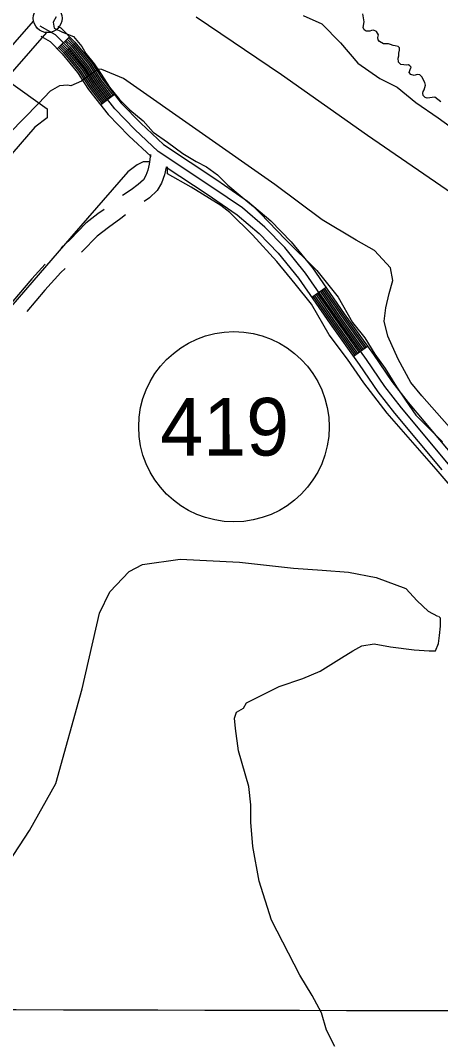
# Model space of a CAD drawing. Extents: x 3192927 to 3230760, y 831141 to 856475.
# Drawn here: x 3198677 to 3199405, y 842548 to 844320 of the extents above; entities that cross this region are included whole.
import ezdxf

# ---------------------------------------------------------------- set-up
doc = ezdxf.new("R2010")
doc.units = 0
for name, color, linetype in [('V-GRID-MAJR', 7, 'Continuous'), ('V-LEVE-TOET', 7, 'Continuous'), ('V-ROAD-CNTR', 7, 'Continuous'), ('V-ROAD-IDEN', 7, 'Continuous'), ('V-SITE-VEGE', 7, 'Continuous'), ('V-SURV-LINE', 7, 'Continuous'), ('V-TOPO-SHOR', 7, 'Continuous')]:
    doc.layers.add(name, color=color, linetype=linetype)

msp = doc.modelspace()

# ---------------------------------------------------------------- linework, layer by layer
at = {"layer": 'V-GRID-MAJR'}
msp.add_spline([(3197116.114, 842608.466), (3202348.431, 842596.67), (3207580.75, 842585.635), (3212813.071, 842575.361), (3218045.394, 842565.848), (3223277.717, 842557.096), (3228510.042, 842549.106), (3228510.043, 842549.106)], degree=3, dxfattribs=at)
at = {"layer": 'V-LEVE-TOET'}
for points in [[(3198981.377, 844326.688), (3199129.132, 844226.932), (3199278.042, 844121.2980000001), (3199443.6580000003, 844007.464)], [(3199511.485, 843511.42), (3199371.9590000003, 843669.481), (3199353.343, 843692.6780000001), (3199331.241, 843733.186), (3199313.022, 843772.9500000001), (3199307.142, 843798.767), (3199309.647, 843821.782), (3199315.779, 843846.985), (3199322.17, 843869.581), (3199317.8140000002, 843891.136), (3199290.275, 843921.698), (3199258.199, 843939.37), (3199199.245, 843974.59), (3199117.514, 844035.706), (3198855.103, 844219.471), (3198817.7830000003, 844235.321), (3198812.27, 844235.777), (3198795.623, 844225.042), (3198782.381, 844214.959), (3198763.9960000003, 844207.277), (3198758.497, 844208.385), (3198744.491, 844207.0970000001), (3198728.34, 844197.736), (3198708.321, 844176.117), (3198632.379, 844099.616)]]:
    msp.add_lwpolyline(points, dxfattribs=at)
at = {"layer": 'V-ROAD-CNTR'}
for p, q in [((3198762.013439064, 844292.17438816), (3198740.622481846, 844271.1414302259)), ((3198839.572283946, 844192.2045881), (3198815.8583313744, 844173.8306248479)), ((3199206.2185506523, 843857.133258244), (3199181.498600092, 843840.13529224)), ((3199278.01440706, 843755.1854621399), (3199253.641455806, 843737.693497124))]:
    msp.add_line(p, q, dxfattribs=at)
for points in [[(3199418.438126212, 843551.0108704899), (3199336.70928967, 843648.528675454), (3199308.2033466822, 843685.3856017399), (3199276.0344110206, 843732.2185080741), (3199225.366512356, 843802.8143668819), (3199170.6636217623, 843882.3652077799), (3199134.7446936, 843926.737119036), (3199100.37476234, 843962.1700481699), (3199061.305840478, 843995.21998207), (3199008.427946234, 844031.4379096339), (3198915.478132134, 844093.3227858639), (3198874.906213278, 844131.285709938), (3198840.1722827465, 844166.940638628), (3198807.168348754, 844209.535553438), (3198787.834387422, 844239.3044938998), (3198760.1834427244, 844272.6414272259), (3198737.51048807, 844295.7003811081), (3198711.196540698, 844310.735351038)], [(3198741.539480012, 844310.673351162), (3198746.7524695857, 844307.6953571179), (3198771.323420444, 844282.7054070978), (3198799.938363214, 844248.207476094), (3198819.4083242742, 844218.2295360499), (3198851.5092600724, 844176.7996189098), (3198885.408192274, 844142.0016885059), (3198924.8221134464, 844105.1217622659), (3199016.8229294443, 844043.8688847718), (3199070.411822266, 844007.1649581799), (3199110.6267418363, 843973.1450262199), (3199145.9796711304, 843936.698099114), (3199182.6915977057, 843891.3471898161), (3199237.6404878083, 843811.438349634), (3199288.310386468, 843740.838490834), (3199320.327322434, 843694.227584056), (3199348.3942663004, 843657.9386566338), (3199429.8431034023, 843560.754851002)], [(3198712.2565385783, 844292.8543867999), (3198728.2685065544, 844283.705405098), (3198749.043465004, 844262.5774473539), (3198775.73041163, 844230.401511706), (3198794.928373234, 844200.8415708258), (3198828.83530542, 844157.081658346), (3198864.404234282, 844120.56973137), (3198903.2712936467, 844084.202532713)], [(3198757.734447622, 844287.9673965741), (3198766.867429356, 844278.680415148), (3198795.096372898, 844244.6464832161), (3198814.512334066, 844214.7515430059), (3198834.829293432, 844188.5295954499)], [(3198759.873443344, 844290.071392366), (3198769.0954249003, 844280.6934111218), (3198797.5173680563, 844246.4274796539), (3198816.9603291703, 844216.490539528), (3198837.2012886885, 844190.367591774)], [(3198742.761477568, 844273.2434260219), (3198751.271460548, 844264.5894433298), (3198778.151406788, 844232.1815081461), (3198797.3763683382, 844202.580567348), (3198818.229326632, 844175.6676211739)], [(3198744.90047329, 844275.347421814), (3198753.499456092, 844266.6024393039), (3198780.572401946, 844233.9625045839), (3198799.824363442, 844204.31956387), (3198820.601321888, 844177.505617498)], [(3198747.0394690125, 844277.450417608), (3198755.7274516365, 844268.6154352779), (3198782.9933971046, 844235.7435010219), (3198802.2723585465, 844206.057560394), (3198822.972317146, 844179.342613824)], [(3198749.178464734, 844279.5544134), (3198757.9554471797, 844270.628431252), (3198785.413392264, 844237.523497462), (3198804.72035365, 844207.796556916), (3198825.344312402, 844181.180610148)], [(3198751.317460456, 844281.657409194), (3198760.1834427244, 844272.6414272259), (3198787.834387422, 844239.3044938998), (3198807.168348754, 844209.535553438), (3198827.7153076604, 844183.017606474)], [(3198753.4564561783, 844283.7604049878), (3198762.411438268, 844274.6544232), (3198790.2553825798, 844241.0854903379), (3198809.6163438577, 844211.2745499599), (3198830.086302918, 844184.8546027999)], [(3198755.5954519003, 844285.86440078), (3198764.6394338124, 844276.667419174), (3198792.67537774, 844242.8654867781), (3198812.064338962, 844213.0135464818), (3198832.458298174, 844186.6925991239)], [(3198902.33165597, 844088.1349026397), (3198899.9860723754, 844071.0073177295), (3198897.795833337, 844061.0260365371), (3198894.1060766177, 844051.2850461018), (3198890.0349750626, 844044.2667580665), (3198881.0279469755, 844035.6818473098), (3198868.475024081, 844026.6578139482), (3198853.7538597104, 844016.667212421)], [(3198929.638072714, 844066.4215309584), (3198929.5459276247, 844065.7486822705), (3198926.6281666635, 844052.4519634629), (3198921.2899233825, 844038.3589538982), (3198913.8350249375, 844025.5072419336), (3198900.2240530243, 844012.5341526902), (3198891.3739057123, 844006.1719671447)], [(3198929.420013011, 844066.0203190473), (3199000.032963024, 844019.006934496), (3199052.19985869, 843983.27500596), (3199090.122782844, 843951.1950701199), (3199123.5097160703, 843916.7761389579), (3199158.6356458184, 843873.383225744), (3199213.0925369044, 843794.19038413), (3199263.758435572, 843723.5985253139), (3199296.0793709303, 843676.5436194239), (3199325.02431304, 843639.118694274), (3199407.033149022, 843541.266889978)], [(3198821.687880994, 843992.8095832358), (3198811.1421859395, 843985.1314286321), (3198789.9429056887, 843968.5898203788), (3198762.696069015, 843940.6786510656), (3198747.6443380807, 843925.9483295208)], [(3198858.5430456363, 843983.3438488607), (3198850.556965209, 843976.7194646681), (3198829.203814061, 843961.172571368), (3198809.9950943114, 843946.1841796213), (3198783.923930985, 843919.4773489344), (3198782.8348037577, 843918.4114785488)], [(3198719.4150827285, 843897.6254443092), (3198696.3882760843, 843872.3336925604), (3198653.8361834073, 843822.1495650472)], [(3198754.2472254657, 843890.4343493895), (3198746.833532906, 843883.1789662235), (3198718.927723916, 843852.5283074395), (3198687.771310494, 843815.7837591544)], [(3199186.4425902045, 843843.5342854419), (3199218.0015270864, 843797.6403772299), (3199258.5154460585, 843741.191490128)], [(3199188.91458526, 843845.234282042), (3199220.456522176, 843799.36537378), (3199260.953441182, 843742.9414866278)], [(3199191.3865803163, 843846.934278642), (3199222.911517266, 843801.0893703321), (3199263.390436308, 843744.69048313)], [(3199193.8585753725, 843848.6342752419), (3199225.366512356, 843802.8143668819), (3199265.8274314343, 843746.439479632)], [(3199196.330570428, 843850.334271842), (3199227.8215074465, 843804.539363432), (3199268.26442656, 843748.1884761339)], [(3199198.8025654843, 843852.034268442), (3199230.2765025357, 843806.2633599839), (3199270.7014216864, 843749.937472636)], [(3199201.2745605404, 843853.7342650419), (3199232.7314976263, 843807.988356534), (3199273.13941681, 843751.687469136)], [(3199203.7465555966, 843855.4332616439), (3199235.185492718, 843809.7133530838), (3199275.576411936, 843753.436465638)], [(3199183.970595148, 843841.8352888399), (3199215.547531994, 843795.9153806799), (3199256.078450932, 843739.4424936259)]]:
    msp.add_lwpolyline(points, dxfattribs=at)
at = {"layer": 'V-ROAD-IDEN'}
msp.add_circle((3199046.712039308, 843615.7140555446), 164.9996700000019, dxfattribs=at)
at = {"layer": 'V-SITE-VEGE'}
for p, q in [((3199166.305, 844329.201), (3199198.903, 844314.377)), ((3199272.506, 844317.9550000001), (3199270.163, 844331.81)), ((3199198.903, 844314.3769999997), (3199231.501, 844281.7629999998)), ((3199270.421, 844308.326), (3199272.506, 844317.9550000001)), ((3199271.97, 844304.17), (3199270.421, 844308.326)), ((3199275.83, 844302.018), (3199271.97, 844304.17)), ((3199282.001, 844301.6639999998), (3199275.83, 844302.0179999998)), ((3199285.122, 844303.03), (3199282.001, 844301.664)), ((3199288.4250000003, 844303.363), (3199285.122, 844303.03)), ((3199293.5270000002, 844301.387), (3199288.4250000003, 844303.363)), ((3199297.2970000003, 844295.5299999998), (3199293.5270000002, 844301.387)), ((3199296.161, 844291.0259999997), (3199297.2970000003, 844295.5299999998)), ((3199296.679, 844286.8949999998), (3199296.161, 844291.0259999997)), ((3199299.083, 844284.159), (3199296.679, 844286.8949999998)), ((3199231.501, 844281.7629999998), (3199261.136, 844246.1849999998)), ((3199305.782, 844280.086), (3199299.083, 844284.159)), ((3199310.3000000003, 844279.5659999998), (3199305.782, 844280.086)), ((3199314.216, 844279.6759999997), (3199310.3000000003, 844279.5659999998)), ((3199317.9, 844278.7649999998), (3199314.216, 844279.6759999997)), ((3199322.594, 844277.0040000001), (3199317.9, 844278.765)), ((3199326.082, 844276.3029999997), (3199322.594, 844277.0040000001)), ((3199331.196, 844274.943), (3199326.082, 844276.3029999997)), ((3199333.61, 844272.621), (3199331.196, 844274.943)), ((3199332.363, 844263.589), (3199333.526, 844269.1229999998)), ((3199333.526, 844269.1229999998), (3199333.61, 844272.621)), ((3199331.1180000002, 844254.764), (3199332.046, 844258.8599999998)), ((3199331.9930000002, 844248.1529999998), (3199331.1180000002, 844254.764)), ((3199332.046, 844258.8599999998), (3199332.363, 844263.589)), ((3199261.136, 844246.1849999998), (3199299.661, 844219.502)), ((3199335.804, 844243.9429999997), (3199331.9930000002, 844248.1529999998)), ((3199341.1410000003, 844243.1950000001), (3199335.804, 844243.943)), ((3199345.044, 844242.8959999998), (3199341.1410000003, 844243.1949999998)), ((3199348.7660000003, 844243.425), (3199345.044, 844242.8959999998)), ((3199351.401, 844241.7139999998), (3199348.7660000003, 844243.425)), ((3199350.293, 844230.002), (3199351.664, 844235.5289999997)), ((3199353.4, 844239.193), (3199351.401, 844241.7139999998)), ((3199351.664, 844235.5289999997), (3199353.4, 844239.193)), ((3199299.661, 844219.502), (3199329.295, 844204.6780000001)), ((3199353.099, 844226.639), (3199350.293, 844230.002)), ((3199358.61, 844224.6510000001), (3199353.099, 844226.639)), ((3199363.81, 844226.7930000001), (3199358.61, 844224.6510000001)), ((3199368.736, 844226.0569999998), (3199363.81, 844226.7930000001)), ((3199372.551, 844222.0519999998), (3199368.736, 844226.0569999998)), ((3199374.31, 844218.0970000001), (3199372.551, 844222.0519999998)), ((3199377.069, 844212.883), (3199374.31, 844218.0970000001)), ((3199329.295, 844204.6780000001), (3199361.893, 844177.9949999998)), ((3199374.63, 844197.084), (3199375.943, 844200.3470000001)), ((3199375.943, 844200.3470000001), (3199378.597, 844207.904)), ((3199378.597, 844207.904), (3199377.069, 844212.883)), ((3199374.142, 844194.006), (3199374.63, 844197.084)), ((3199374.2630000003, 844190.5019999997), (3199374.142, 844194.006)), ((3199378.0810000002, 844186.4979999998), (3199374.2630000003, 844190.5019999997)), ((3199381.5640000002, 844185.794), (3199378.0810000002, 844186.498)), ((3199394.788, 844187.5389999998), (3199381.5640000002, 844185.7939999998)), ((3199400.043, 844183.498), (3199394.788, 844187.539)), ((3199404.881, 844179.0579999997), (3199400.043, 844183.498)), ((3199361.893, 844177.9949999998), (3199400.418, 844151.31)), ((3199400.418, 844151.31), (3199421.162, 844136.486))]:
    msp.add_line(p, q, dxfattribs=at)
at = {"layer": 'V-SURV-LINE'}
for points in [[(3197205.3664230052, 842606.2641281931), (3198699.5884682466, 844319.0402083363)], [(3198722.1870033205, 844299.3093604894), (3197227.96421081, 842586.5324237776)]]:
    msp.add_lwpolyline(points, dxfattribs=at)
msp.add_circle((3198724.02069, 844324.2293), 25, dxfattribs=at)
at = {"layer": 'V-TOPO-SHOR'}
for points in [[(3198738.896274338, 844326.3993266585), (3198733.5996722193, 844317.5552056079), (3198735.3763347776, 844306.9489374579), (3198749.525767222, 844299.8887366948), (3198768.979059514, 844292.8328905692), (3198783.1372012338, 844275.1649701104), (3198790.219175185, 844262.7951033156), (3198804.377316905, 844245.1271828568), (3198816.7675053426, 844227.4578108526), (3198830.9300017, 844204.4860305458), (3198848.6269530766, 844183.2851066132), (3198866.321001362, 844165.6200892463), (3198889.32036104, 844146.1914732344), (3198907.0158608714, 844126.7585025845), (3198931.7817222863, 844109.0992914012), (3198958.31698853, 844089.6735784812), (3198981.3119935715, 844075.5488223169), (3198998.998784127, 844066.723571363), (3199018.4578826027, 844052.595912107), (3199036.1519308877, 844034.9308947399), (3199060.920695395, 844013.7357769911), (3199080.3812454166, 843997.8401644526), (3199092.767079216, 843985.4746522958), (3199135.2342466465, 843941.3106573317), (3199190.08579633, 843886.5491034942), (3199227.2505554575, 843840.6128006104), (3199252.0381900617, 843796.4342901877), (3199273.2754026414, 843769.9324094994), (3199290.978160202, 843741.659672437), (3199308.6780146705, 843716.9228419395), (3199328.151628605, 843685.1156498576), (3199344.082078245, 843662.1453210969), (3199361.78338426, 843635.6405373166), (3199377.7080277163, 843619.742021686), (3199407.7879098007, 843589.7114921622)], [(3199293.5270000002, 844301.387), (3199288.4250000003, 844303.363), (3199285.122, 844303.03), (3199282.001, 844301.664), (3199275.83, 844302.018), (3199271.97, 844304.17), (3199270.421, 844308.326), (3199272.506, 844317.9550000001), (3199270.163, 844331.81)], [(3199404.881, 844179.058), (3199400.043, 844183.498), (3199394.786, 844187.539), (3199381.5640000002, 844185.796), (3199378.0810000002, 844186.498), (3199374.2630000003, 844190.502), (3199374.142, 844194.006), (3199374.63, 844197.084), (3199375.943, 844200.3470000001), (3199378.597, 844207.904), (3199377.069, 844212.883), (3199374.31, 844218.0970000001), (3199372.551, 844222.052), (3199368.736, 844226.057), (3199363.81, 844226.7930000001), (3199358.61, 844224.653), (3199353.097, 844226.639), (3199350.296, 844230.002), (3199351.664, 844235.529), (3199353.4, 844239.193), (3199351.401, 844241.714), (3199348.7660000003, 844243.425), (3199345.044, 844242.8960000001), (3199341.1410000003, 844243.1950000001), (3199335.804, 844243.943), (3199331.9930000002, 844248.153), (3199331.12, 844254.764), (3199332.044, 844258.86), (3199332.363, 844263.589), (3199333.526, 844269.123), (3199333.61, 844272.621), (3199331.196, 844274.943), (3199326.08, 844276.3030000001), (3199322.594, 844277.0040000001), (3199317.9, 844278.765), (3199314.216, 844279.676), (3199310.3000000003, 844279.566), (3199305.782, 844280.086), (3199299.083, 844284.159), (3199296.679, 844286.895), (3199296.161, 844291.0260000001), (3199297.2970000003, 844295.53), (3199293.5270000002, 844301.387)], [(3198655.8939174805, 844214.9500471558), (3198723.1153339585, 844167.2704672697), (3198723.1283978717, 844151.3588877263), (3198701.9260223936, 844135.4298896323), (3198465.245272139, 843861.2026236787), (3198444.06466985, 843818.7543263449), (3198414.0457526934, 843774.5308179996), (3198387.5496781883, 843746.2217922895), (3198375.18126294, 843737.371865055), (3198352.897, 843721.488)], [(3198901.7540958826, 844075.4835027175), (3198889.3784229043, 844075.4733418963), (3198878.775057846, 844070.1607727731), (3198862.873639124, 844057.7720358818), (3198765.7276559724, 843946.3111440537), (3198615.5938784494, 843772.9283409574)], [(3199736.990106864, 843147.9931590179), (3199708.6767265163, 843179.7930933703), (3199699.8267992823, 843192.1615086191), (3199552.948779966, 843359.9965921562), (3199397.2193818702, 843541.9680442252), (3199312.2777892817, 843639.1358005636), (3199271.571317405, 843692.1410134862), (3199243.2506793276, 843732.7807142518), (3199211.3926831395, 843775.185465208), (3199181.293930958, 843828.1993874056), (3199152.9776475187, 843863.5352283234), (3199121.122554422, 843902.4040727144), (3199078.6539354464, 843948.3360209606), (3199039.7270292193, 843987.1990591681), (3199023.8052888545, 843999.5616682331), (3198972.508515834, 844031.3427324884), (3198931.8267202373, 844054.2927396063), (3198931.816559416, 844066.6684125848)], [(3198618.1253448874, 842842.9863658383), (3198657.0058016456, 842860.697832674), (3198692.319869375, 842915.533415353), (3198738.2198836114, 842996.8970065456), (3198784.0516751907, 843161.3544020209), (3198813.999466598, 843292.2076212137), (3198831.6485169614, 843329.3491556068), (3198865.2105984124, 843364.7358006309), (3198888.183830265, 843377.1303437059), (3198953.590843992, 843386.0238173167), (3199056.13648902, 843380.8041471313), (3199149.846722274, 843370.2733593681), (3199199.3523172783, 843366.7780960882), (3199245.322005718, 843363.2799297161), (3199293.064002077, 843354.4793550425), (3199344.350614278, 843335.0739637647), (3199363.815518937, 843313.8744913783), (3199383.2775205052, 843296.2109255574), (3199399.196357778, 843287.3842230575)], [(3199221.245628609, 842541.1613316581), (3199207.0787776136, 842569.4369718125), (3199198.2143349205, 842599.4849198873), (3199182.2780790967, 842629.5270617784), (3199161.0336087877, 842664.8687088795), (3199111.4525333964, 842760.2975428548), (3199090.181935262, 842827.4623490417), (3199079.5248630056, 842887.5640513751), (3199075.954119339, 842929.9920270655), (3199075.9294430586, 842960.0472328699), (3199072.367408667, 842991.8674888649), (3199054.6370717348, 843053.7313382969), (3199049.3012778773, 843092.6219558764), (3199047.5188091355, 843110.3000371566), (3199051.0460064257, 843120.9106599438), (3199063.41587322, 843127.9926338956), (3199068.7124753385, 843136.8367549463), (3199125.2637556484, 843165.1704569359), (3199165.915068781, 843179.3474687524), (3199195.960113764, 843191.7478180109), (3199233.0682626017, 843214.7616931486), (3199252.505587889, 843227.1533331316), (3199268.409909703, 843236.0061634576), (3199289.622446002, 843239.5594885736), (3199317.9140531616, 843234.2788534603), (3199358.581333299, 843229.008379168), (3199385.102084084, 843227.262199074), (3199395.7098037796, 843227.2709083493), (3199401.003502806, 843239.6509359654), (3199402.7598437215, 843253.7960137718), (3199404.5147330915, 843269.7090448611), (3199404.5031207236, 843283.8526711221), (3199400.9643110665, 843287.3856745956)]]:
    msp.add_lwpolyline(points, dxfattribs=at)

# ---------------------------------------------------------------- texts
at = {"layer": 'V-ROAD-IDEN'}
msp.add_text('419', height=99.99983799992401, rotation=0.046969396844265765, dxfattribs=at).set_placement((3198919.194294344, 843565.6091557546))

doc.saveas('drawing.dxf')
